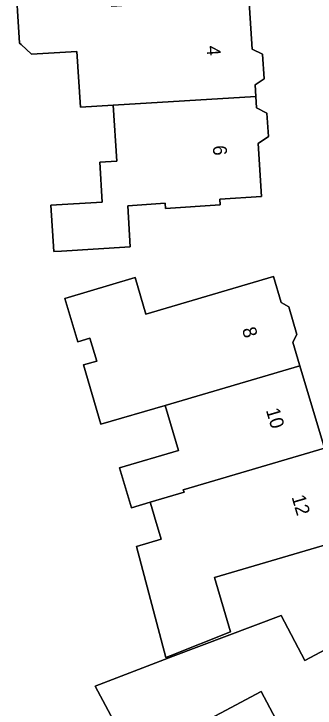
# Model space of a CAD drawing. Extents: x 161347 to 161881, y 382161 to 382804.
# Drawn here: x 161447.2 to 161469, y 382310.5 to 382360.9 of the extents above; entities that cross this region are included whole.
import ezdxf

# ---------------------------------------------------------------- set-up
doc = ezdxf.new("R2010")
doc.units = 0
for name, color, linetype in [('IMGEO_Erf', 7, 'Continuous'), ('IMGEO_Pand', 7, 'Continuous'), ('IMGEO_Pand_nummerreeks', 7, 'Continuous')]:
    doc.layers.add(name, color=color, linetype=linetype)

msp = doc.modelspace()

# ---------------------------------------------------------------- linework, layer by layer
at = {"layer": 'IMGEO_Erf'}
for points in [[(161464.198, 382362.095), (161464.435, 382358.327), (161465.186, 382357.953), (161465.298, 382356.172), (161464.645, 382355.738), (161464.698, 382354.898), (161464.751, 382354.056), (161465.506, 382353.681), (161465.613, 382351.982), (161464.858, 382351.481), (161465.1, 382347.636), (161462.095, 382347.447), (161462.122, 382347.024), (161458.163, 382346.775), (161458.139, 382347.144), (161455.423, 382346.973), (161455.609, 382343.989), (161450.619, 382343.678), (161450.079, 382343.644), (161449.868, 382347.001), (161453.585, 382347.235), (161453.403, 382350.131), (161454.632, 382350.208), (161454.377, 382354.255), (161452, 382354.124), (161451.747, 382358.156), (161448.456, 382357.949), (161447.699, 382358.647), (161447.592, 382358.746), (161447.271, 382363.854)], [(161471.563, 382322.92), (161461.712, 382320.009), (161462.877, 382316.067), (161458.504, 382314.347), (161458.192, 382314.224), (161456.058, 382322.257), (161457.844, 382322.784), (161457.364, 382324.406), (161457.139, 382325.168), (161457.05, 382325.47), (161455.689, 382325.067), (161454.833, 382327.966), (161459.09, 382329.223), (161458.129, 382332.474), (161453.48, 382331.124), (161452.21, 382335.424), (161453.179, 382335.71), (161452.689, 382337.37), (161451.801, 382337.108), (161450.872, 382340.252), (161455.952, 382341.755), (161456.734, 382339.105), (161465.979, 382341.834), (161466.537, 382339.945), (161467.086, 382339.646), (161467.68, 382337.634), (161467.382, 382337.086), (161467.868, 382335.442), (161467.896, 382335.364), (161469.662, 382329.389)]]:
    msp.add_lwpolyline(points, dxfattribs=at)
msp.add_lwpolyline([(161473.729, 382316.918), (161477.514, 382309.794), (161477.004, 382309.524), (161477.33, 382308.911), (161474.644, 382307.484), (161474.333, 382308.07), (161469.531, 382305.518), (161468.703, 382307.077), (161467.82, 382306.608), (161465.09, 382311.746), (161455.881, 382306.854), (161453.078, 382312.13), (161458.706, 382314.316), (161466.527, 382317.259), (161468.254, 382314.009)], close=True, dxfattribs=at)
at = {"layer": 'IMGEO_Pand'}
for points in [[(161454.029, 382365.47), (161447.284, 382365.26), (161447.183, 382365.257), (161447.271, 382363.854), (161447.592, 382358.746), (161447.699, 382358.647), (161448.456, 382357.949), (161451.747, 382358.156), (161452, 382354.124), (161454.377, 382354.255), (161464.698, 382354.898), (161464.645, 382355.738), (161465.298, 382356.172), (161465.186, 382357.953), (161464.435, 382358.327), (161464.198, 382362.095), (161461.156, 382361.903), (161461.129, 382362.334), (161457.17, 382362.086), (161457.201, 382361.599), (161454.282, 382361.415)], [(161464.698, 382354.898), (161454.377, 382354.255), (161454.632, 382350.208), (161453.403, 382350.131), (161453.585, 382347.235), (161449.868, 382347.001), (161450.079, 382343.644), (161450.619, 382343.678), (161455.609, 382343.989), (161455.423, 382346.973), (161458.139, 382347.144), (161458.163, 382346.775), (161462.122, 382347.024), (161462.095, 382347.447), (161465.1, 382347.636), (161464.858, 382351.481), (161465.613, 382351.982), (161465.506, 382353.681), (161464.751, 382354.056)], [(161467.68, 382337.634), (161467.086, 382339.646), (161466.537, 382339.945), (161465.979, 382341.834), (161456.734, 382339.105), (161455.952, 382341.755), (161450.872, 382340.252), (161451.801, 382337.108), (161452.689, 382337.37), (161453.179, 382335.71), (161452.21, 382335.424), (161453.48, 382331.124), (161458.129, 382332.474), (161467.896, 382335.364), (161467.868, 382335.442), (161467.382, 382337.086)], [(161469.662, 382329.389), (161467.896, 382335.364), (161458.129, 382332.474), (161459.09, 382329.223), (161454.833, 382327.966), (161455.689, 382325.067), (161457.05, 382325.47), (161459.503, 382326.197), (161459.45, 382326.375)], [(161469.662, 382329.389), (161459.45, 382326.375), (161459.503, 382326.197), (161457.05, 382325.47), (161457.139, 382325.168), (161457.364, 382324.406), (161457.844, 382322.784), (161456.058, 382322.257), (161458.192, 382314.224), (161458.504, 382314.347), (161462.877, 382316.067), (161461.712, 382320.009), (161471.563, 382322.92), (161471.006, 382324.807), (161471.332, 382325.408), (161470.747, 382327.391), (161470.156, 382327.712)], [(161477.514, 382309.794), (161473.729, 382316.918), (161468.254, 382314.009), (161466.527, 382317.259), (161458.706, 382314.316), (161453.078, 382312.13), (161455.881, 382306.854), (161465.09, 382311.746), (161467.82, 382306.608), (161468.703, 382307.077), (161469.531, 382305.518), (161474.333, 382308.07), (161474.644, 382307.484), (161477.33, 382308.911), (161477.004, 382309.524)]]:
    msp.add_lwpolyline(points, close=True, dxfattribs=at)

# ---------------------------------------------------------------- texts
at = {"layer": 'IMGEO_Pand_nummerreeks'}
for s, rotation, p in [('4', 273.5693, (161461.132, 382358.552)), ('6', 273.5693, (161461.583, 382351.322)), ('8', 286.4494, (161463.686, 382338.014)), ('10', 286.4494, (161465.418, 382332.152)), ('12', 286.4494, (161467.277, 382325.852))]:
    msp.add_text(s, height=1, rotation=rotation, dxfattribs=at).set_placement(p)

doc.saveas('drawing.dxf')
